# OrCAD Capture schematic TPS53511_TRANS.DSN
size D; title: TPS53511,  4.5-Vto18-VInput, 1.5-AStep-Down Regulator; rev: 1.0; note: Datasheet: SLUSBG4   EVM:
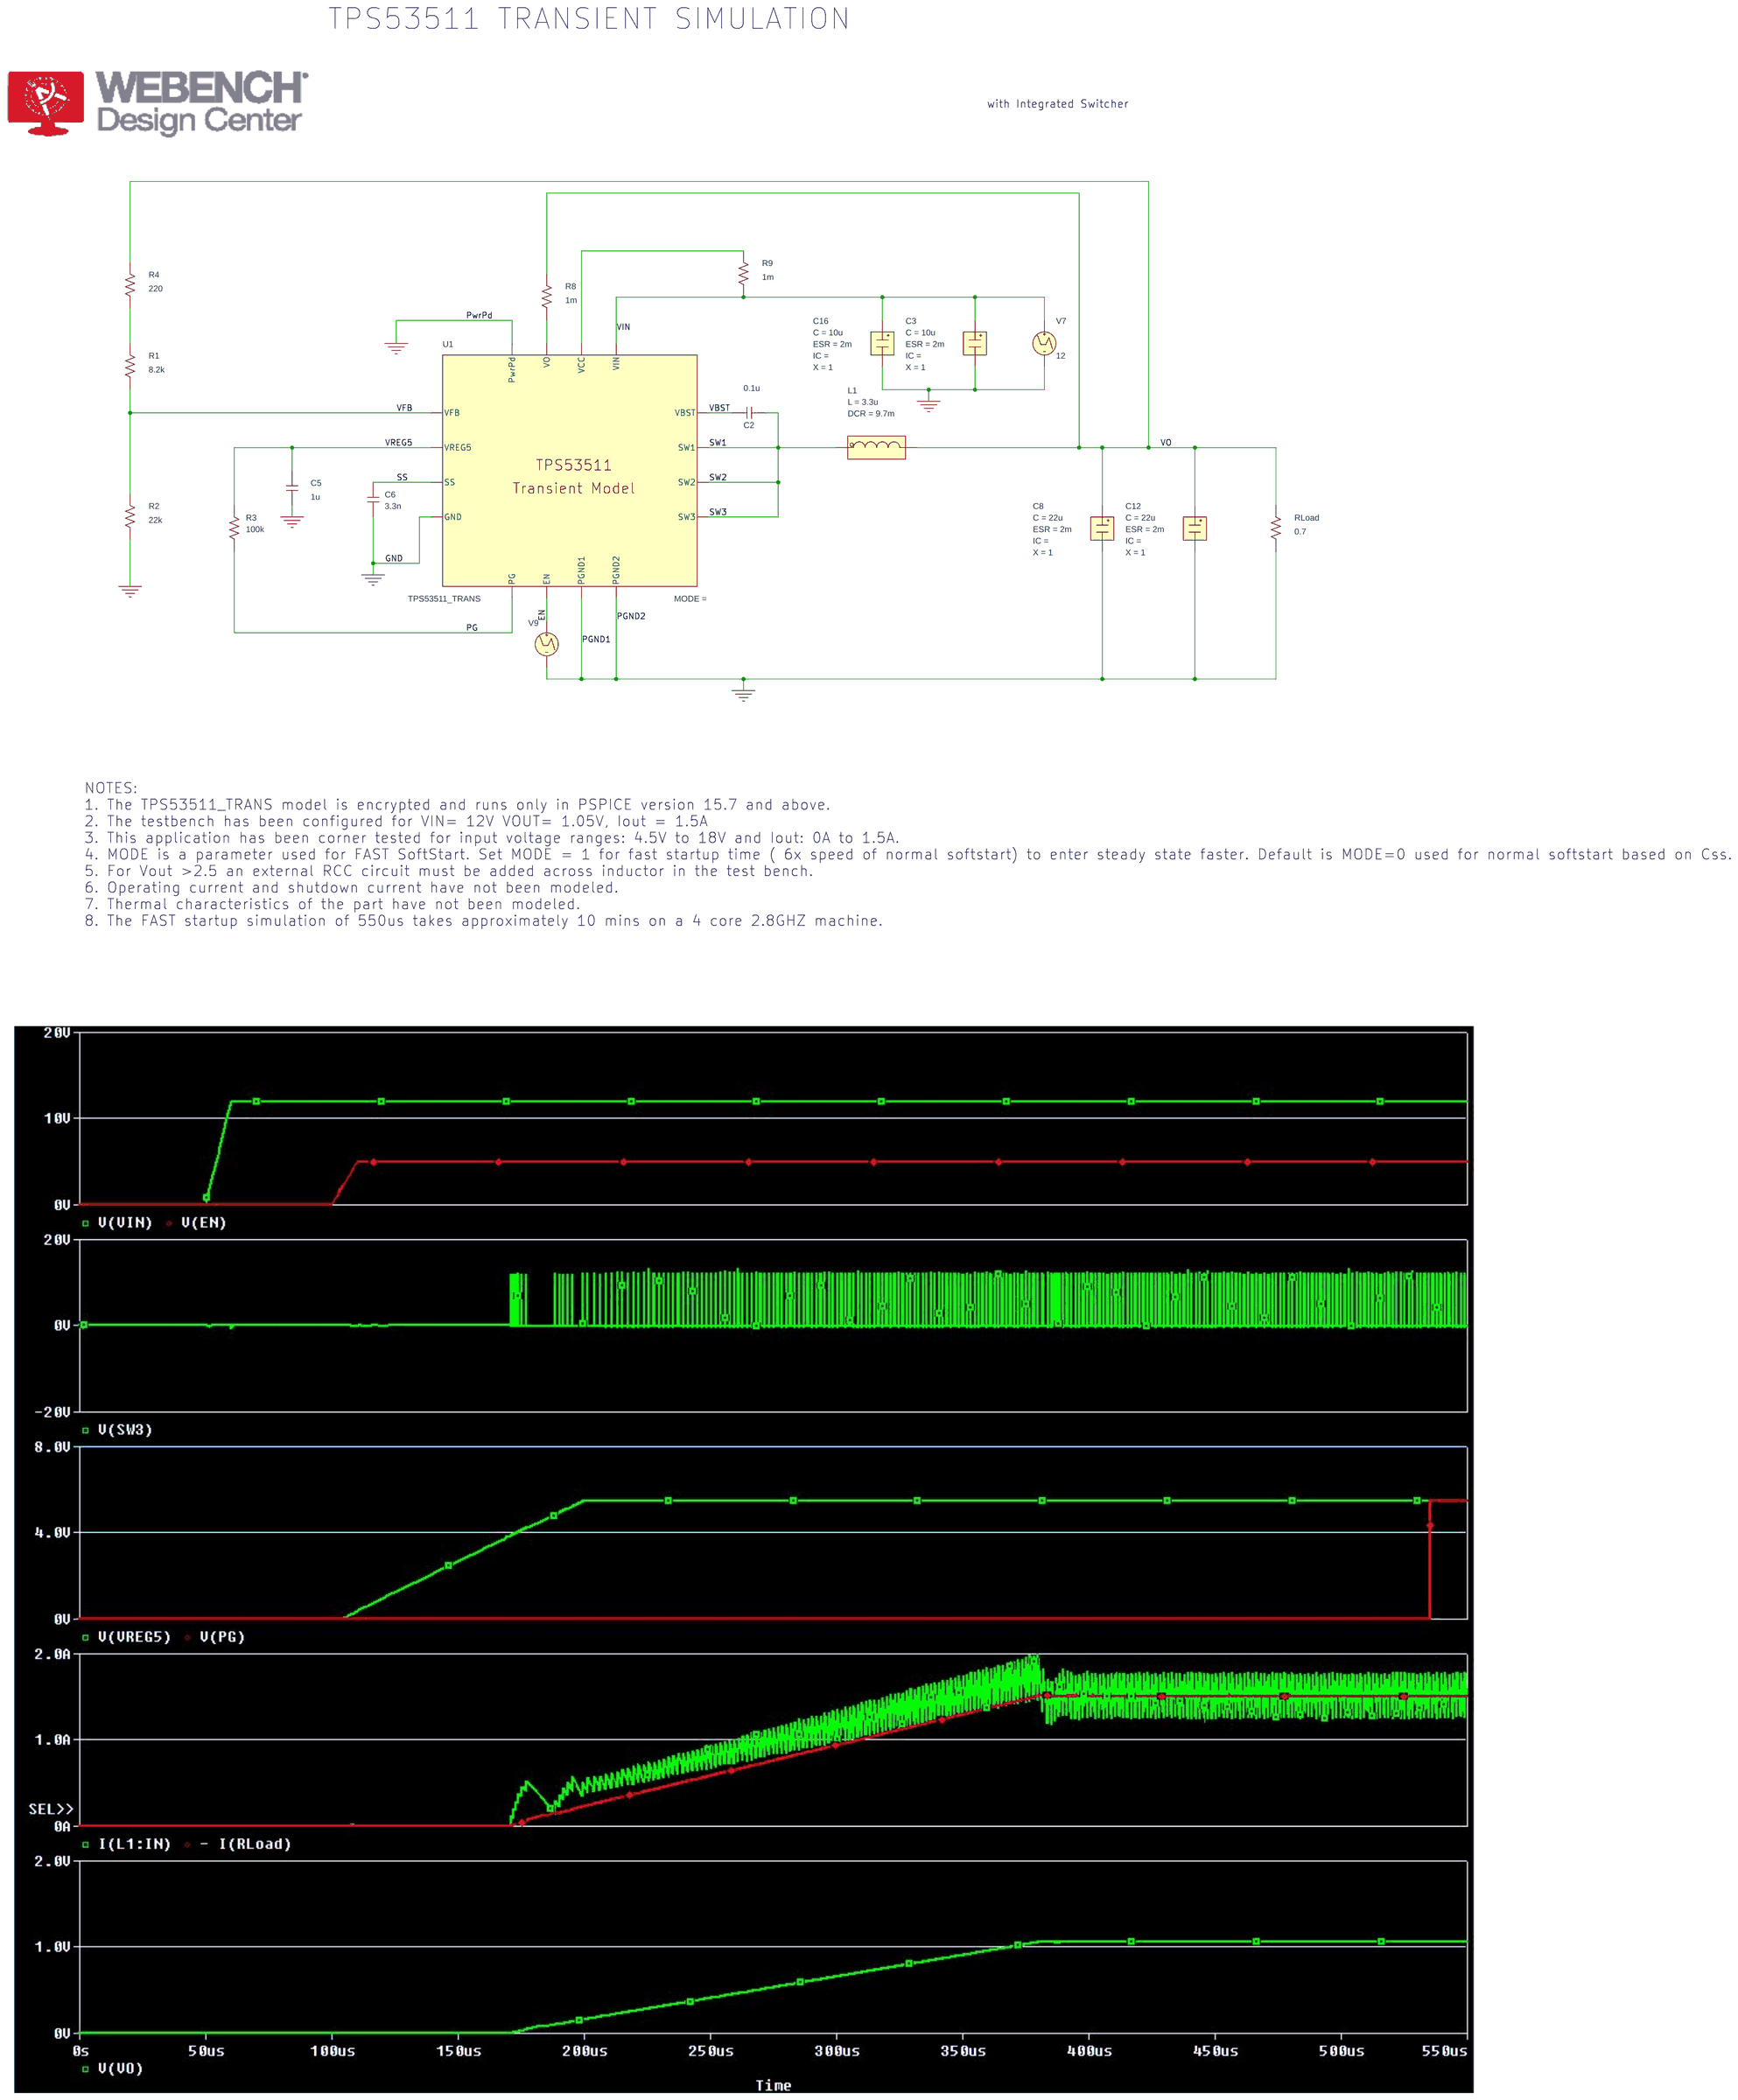
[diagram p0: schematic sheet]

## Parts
C2  0.1u  [RAD/CK05]
C3  CESR
C5  1u  [RAD/CK05]
C6  3.3n  [RAD/CK05]
C8  CESR
C12  CESR
C16  CESR
L1  LDCR
R1  8.2k  [AX/RC05]
R2  22k  [AX/RC05]
R3  100k  [AX/RC05]
R4  220  [AX/RC05]
R8  1m  [AX/RC05]
R9  1m  [AX/RC05]
RLoad  0.7  [AX/RC05]
U1  TPS53511_TRANS
V7  VPWL
V9  VPWL

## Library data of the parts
C2 C5 C6 = C: IC: 0
C3 C16 = CESR: C: 10u; ESR: 2m; PSpiceTemplate: X^@REFDES %IN %OUT @MODEL PARAMS:  ?C|C=@C||C=100u|  ?ESR|ESR=@ESR||ESR=0.01| ?X|X=@X||X=2|  ?IC|IC=@IC||IC=2|; X: 1
C8 C12 = CESR: C: 22u; ESR: 2m; PSpiceTemplate: X^@REFDES %IN %OUT @MODEL PARAMS:  ?C|C=@C||C=100u|  ?ESR|ESR=@ESR||ESR=0.01| ?X|X=@X||X=2|  ?IC|IC=@IC||IC=2|; X: 1
L1 = LDCR: DCR: 9.7m; IC: 0; L: 3.3u; PSpiceTemplate: X^@REFDES %IN %OUT @MODEL PARAMS:  ?L|L=@L||L=1u|  ?DCR|DCR=@DCR||DCR=0.01| ?IC|IC=@IC||IC=0|
R1-R4 R8 R9 RLoad = R
U1 = TPS53511_TRANS
V7 = VPWL: PSpiceTemplate: V^@REFDES %+ %- ?DC|DC @DC| ?AC|AC @AC|\n+PWL @T1 @V1 @T2 @V2 #T3/@T3 @V3/ #T4/@T4 @V4/ #T5/@T5 @V5/ #T6/@T6 @V6/ #T7/@T7 @V7/ #T8/@T8 @V8/ #T9/@T9 @V9/ #T10/@T10 @V10/; T1: 0; T2: .05m; T3: .06m; V1: 0; V2: 0; V3: 12
V9 = VPWL: PSpiceTemplate: V^@REFDES %+ %- ?DC|DC @DC| ?AC|AC @AC|\n+PWL @T1 @V1 @T2 @V2 #T3/@T3 @V3/ #T4/@T4 @V4/ #T5/@T5 @V5/ #T6/@T6 @V6/ #T7/@T7 @V7/ #T8/@T8 @V8/ #T9/@T9 @V9/ #T10/@T10 @V10/; T1: 0; T2: .1m; T3: .11m; T4: .6m; V1: 0; V2: 0; V3: 5; V4: 5

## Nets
VIN: C3.1(IN) C16.1(IN) R9.1 U1.VIN V7.1(+)
0: C3.3(OUT) C5.1 C6.1 C8.3(OUT) C12.3(OUT) C16.3(OUT) R2.1 RLoad.1 U1.GND U1.PGND1 U1.PGND2 U1.PwrPd V7.2(-) V9.2(-)
EN: U1.EN V9.1(+)
PG: R3.1 U1.PG
SS: C6.2 U1.SS
SW1: C2.1 L1.1(IN) U1.SW1 U1.SW2 U1.SW3
VBST: C2.2 U1.VBST
VFB: R1.1 R2.2 U1.VFB
VO: C8.1(IN) C12.1(IN) L1.3(OUT) R4.2 R8.2 RLoad.2
VREG5: C5.2 R3.2 U1.VREG5
N13364355: R1.2 R4.1
N16776666: R9.2 U1.VCC
N16784783: R8.1 U1.VO

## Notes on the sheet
- TPS53511 TRANSIENT SIMULATION
- with Integrated Switcher
- NOTES:
  1. The TPS53511_TRANS model is encrypted and runs only in PSPICE version 15.7 and above.
  2. The testbench has been configured for VIN= 12V VOUT= 1.05V, Iout = 1.5A
  3. This application has been corner tested for input voltage ranges: 4.5V to 18V and Iout: 0A to 1.5A.
  4. MODE is a parameter used for FAST SoftStart. Set MODE = 1 for fast startup time ( 6x speed of normal softstart) to enter steady state faster. Default is MODE=0 used for normal softstart based on Css.
  5. For Vout >2.5 an external RCC circuit must be added across inductor in the test bench.
  6. Operating current and shutdown current have not been modeled.
  7. Thermal characteristics of the part have not been modeled.
  8. The FAST startup simulation of 550us takes approximately 10 mins on a 4 core 2.8GHZ machine.
